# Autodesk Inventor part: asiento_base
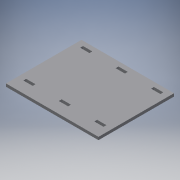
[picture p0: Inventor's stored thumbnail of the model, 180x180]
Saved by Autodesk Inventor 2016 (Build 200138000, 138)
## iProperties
Created: 2017-06
Part Number: asiento_base
Material: Generic
Document SubType Name: Modeling
Designer: laboratorioesan
Density: 1 g/cm^3
Appearance: Default
Author: laboratorioesan
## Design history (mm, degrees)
sketch "Sketch1"
  geometry: L1 (218.5, -350)-(158.5, -350) reference; L2 (158.5, -350)-(158.5, -368.5) reference; L3 (218.5, -368.5)-(158.5, -368.5) reference; L4 (218.5, -350)-(218.5, -368.5) reference; L5 (448.5, -350)-(388.5, -350) reference; L6 (388.5, -350)-(388.5, -368.5) reference; L7 (448.5, -368.5)-(388.5, -368.5) reference; L8 (448.5, -350)-(448.5, -368.5) reference; L9 (678.5, -350)-(618.5, -350) reference; L10 (618.5, -350)-(618.5, -368.5) reference; L11 (678.5, -368.5)-(618.5, -368.5) reference; L12 (678.5, -350)-(678.5, -368.5) reference; L13 (618.5, 0)-(678.5, 0) reference; L14 (678.5, 0)-(678.5, 18.5) reference; L15 (618.5, 18.5)-(678.5, 18.5) reference; L16 (618.5, 0)-(618.5, 18.5) reference; L17 (388.5, 0)-(448.5, 0) reference; L18 (388.5, 0)-(448.5, 0) reference; L19 (448.5, 0)-(448.5, 18.5) reference; L20 (388.5, 18.5)-(448.5, 18.5) reference; L21 (388.5, 0)-(388.5, 18.5) reference; L22 (158.5, 0)-(218.5, 0) reference; L23 (218.5, 0)-(218.5, 18.5) reference; L24 (158.5, 18.5)-(218.5, 18.5) reference; L25 (158.5, 0)-(158.5, 18.5) reference; L26 (118.5, -350)-(118.5, -368.5) reference; L27 (118.5, 0)-(118.5, 18.5) reference; L28 (718.5, -350)-(718.5, -368.5) reference; L29 (718.5, 0)-(718.5, 18.5) reference; L30 (118.5, -441.5)-(718.5, -441.5); L31 (718.5, -441.5)-(718.5, 48.5); L32 (718.5, 48.5)-(118.5, 48.5); L33 (118.5, 48.5)-(118.5, -441.5); 1 further point
  constraints: 8 end point, 2 parallel, 2 vertical alignment, 1 horizontal, 1 perpendicular
  dimensions: "d0" = 490 distance between parallel lines of L32 L30; "d1" = 30 vertical distance of L32.end L24.start
extrude "Extrusion1" new body sketch "Sketch1" distance "d2" = 18.5; taper "d3" = 0 deg
body "Solid1"
node "Reference1"
node "Reference2"
node "Reference3"
node "Reference4"
node "Reference5"
node "Reference6"
node "Reference7"
node "Reference8"
node "Reference9"
node "Reference10"
node "Reference11"
